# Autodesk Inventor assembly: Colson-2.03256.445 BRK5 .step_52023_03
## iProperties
Created: 2010-10
Part Number: Colson-2.03256.445 BRK5 .step_52023_03
Document SubType Name: Assembly
Designer: Administrator
Author: Administrator
